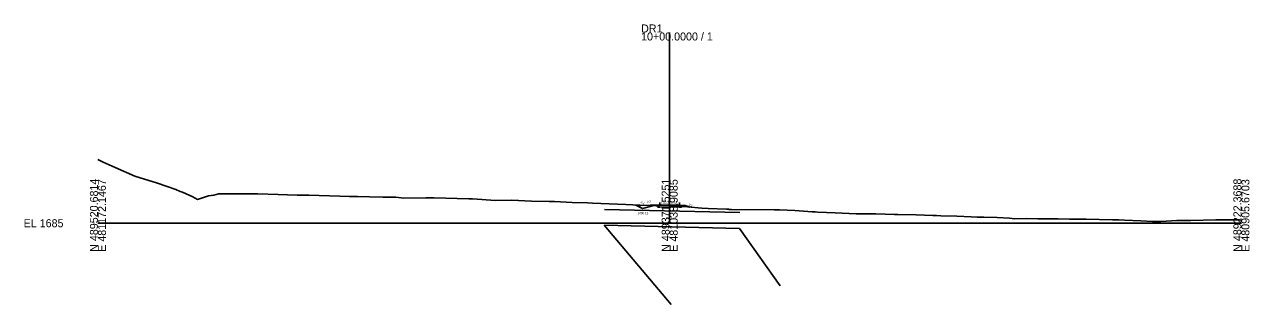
# Model space of a CAD drawing. Extents: x -26 to 403, y -28 to 1060.
# Drawn here: x -25.7 to 402.8, y -28.4 to 69.5 of the extents above; entities that cross this region are included whole.
import ezdxf

# ---------------------------------------------------------------- set-up
doc = ezdxf.new("R2010")
doc.units = 0
for name, color, linetype in [('Exist Cross Section Cell', 7, 'Continuous'), ('Exist XS Center Line Elevation Label', 7, 'Continuous'), ('Exist XS Ground Line', 7, 'Continuous'), ('Prop XS Ditch Slope Text', 7, 'Continuous'), ('Prop XS Ditch Standard Text', 7, 'Continuous'), ('Prop XS Dump Level', 7, 'Continuous'), ('Prop XS Earthwork Shape', 7, 'Continuous'), ('Prop XS EOT Tick Mark', 7, 'Continuous'), ('Prop XS Finish Grade', 7, 'Continuous'), ('Prop XS Finish Grade Earthwork', 7, 'Continuous'), ('Prop XS Finish Grade Pavement', 7, 'Continuous'), ('Prop XS Hydro Typical Ditch Data', 7, 'Continuous'), ('Prop XS Pvmt Edge Slope', 7, 'Continuous'), ('Prop XS SE Text', 7, 'Continuous'), ('Prop XS Shoulder Borrow Shape', 7, 'Continuous'), ('Prop XS Side Slope Text', 7, 'Continuous'), ('Prop XS Subgrade Earthwork', 7, 'Continuous'), ('Scratch_Level_4', 7, 'Continuous'), ('Scratch_Level_5', 7, 'Continuous')]:
    doc.layers.add(name, color=color, linetype=linetype)

msp = doc.modelspace()

# ---------------------------------------------------------------- linework, layer by layer
at = {"layer": 'Exist Cross Section Cell'}
for p, q in [((200, 0), (200, 66.75)), ((0, 0), (200, 0)), ((200, 0), (400, 0))]:
    msp.add_line(p, q, dxfattribs=at)
at = {"layer": 'Exist XS Ground Line'}
msp.add_lwpolyline([(0, 22.25), (1.77, 21.4), (6.02, 19.52), (12.85, 16.44), (20.87, 13.98), (27.26, 11.83), (28.74, 11.16), (29.57, 10.9), (33.18, 9.29), (34.8, 8.36), (36.61, 8.93), (38.72, 9.55), (40.5, 9.84), (42.12, 10.25), (55.9, 10.24), (63.02, 10.01), (66.27, 9.94), (69.66, 9.86), (73.77, 9.77), (77.43, 9.68), (84.67, 9.47), (87.93, 9.41), (90.85, 9.32), (95.02, 9.24), (99.69, 9.14), (102.1, 9.09), (104.26, 9.08), (107.06, 8.79), (114.7, 8.94), (116.27, 8.89), (117.67, 8.87), (129.71, 8.56), (130.44, 8.54), (131.08, 8.51), (139.03, 7.95), (144.73, 8.02), (151.69, 7.71), (157.9, 7.66), (158.77, 7.64), (159.74, 7.61), (165.85, 7.31), (171.31, 7.17), (173.03, 7.05), (184.72, 6.53), (189.54, 6.27), (189.96, 6.26), (196.5, 6.48), (197, 6.44), (198.06, 6.36), (200, 6.21), (203.43, 5.94), (206.2, 5.69), (211.29, 5.25), (213.44, 5.1), (219.9, 4.91), (220.54, 4.88), (220.86, 4.86), (221.68, 4.83), (236.69, 4.73), (238.37, 4.67), (243.77, 4.41), (249.82, 4), (250.86, 3.94), (251.78, 3.89), (257.94, 3.67), (265.19, 3.3), (272.11, 3.26), (278.6, 3.06), (279.19, 3.05), (279.85, 3.03), (286.28, 2.98), (292.02, 2.7), (293.36, 2.66), (294.86, 2.6), (300.44, 2.46), (305.43, 2.19), (307.53, 2.14), (309.88, 2.07), (314.61, 1.96), (318.84, 1.75), (320.78, 1.57), (324.89, 1.6), (328.78, 1.55), (332.25, 1.58), (335.86, 1.59), (339.91, 1.45), (342.95, 1.38), (345.66, 1.37), (354.92, 1.22), (357.11, 1.23), (359.07, 1.11), (364.85, 0.81), (368.95, 0.61), (371.84, 0.6), (377.47, 0.96), (382.26, 0.96), (391.05, 1.21), (399.29, 1.15), (400, 1.13)], dxfattribs=at)
at = {"layer": 'Prop XS Dump Level'}
for p, q in [((200, 6.38), (196.52, 6.31)), ((203.43, 6.31), (200, 6.38))]:
    msp.add_line(p, q, dxfattribs=at)
at = {"layer": 'Prop XS Earthwork Shape'}
for points in [[(203.43, 5.94), (204.34, 5.86), (204.11, 5.63), (203.43, 5.64), (200, 5.71), (196.52, 5.64), (195.83, 5.63), (195.25, 6.21), (194.51, 6.15), (190.51, 5.15), (188.11, 6.35), (189.54, 6.27), (189.96, 6.26), (196.5, 6.48), (197, 6.44), (198.06, 6.36), (200, 6.21)], [(204.34, 5.86), (206.2, 5.69), (207.01, 5.62), (205.43, 6.15), (204.69, 6.21)]]:
    msp.add_lwpolyline(points, close=True, dxfattribs=at)
at = {"layer": 'Prop XS EOT Tick Mark'}
for p, q in [((196.52, 6.31), (196.52, 7.31)), ((203.43, 6.31), (203.43, 7.31))]:
    msp.add_line(p, q, dxfattribs=at)
at = {"layer": 'Prop XS Finish Grade'}
for p, q in [((196.52, 6.31), (195.25, 6.21)), ((203.43, 6.31), (204.69, 6.21))]:
    msp.add_line(p, q, dxfattribs=at)
at = {"layer": 'Prop XS Finish Grade Earthwork'}
for p, q in [((190.51, 5.15), (188.11, 6.35)), ((194.51, 6.15), (190.51, 5.15)), ((195.25, 6.21), (194.51, 6.15)), ((204.69, 6.21), (205.43, 6.15)), ((205.43, 6.15), (207.01, 5.62))]:
    msp.add_line(p, q, dxfattribs=at)
at = {"layer": 'Prop XS Finish Grade Pavement'}
for p, q in [((196.52, 6.31), (200, 6.38)), ((200, 6.38), (203.43, 6.31))]:
    msp.add_line(p, q, dxfattribs=at)
at = {"layer": 'Prop XS Hydro Typical Ditch Data'}
for p, q in [((190.51, 5.15), (188.71, 6.05)), ((194.51, 6.15), (190.51, 5.15))]:
    msp.add_line(p, q, dxfattribs=at)
at = {"layer": 'Prop XS Pvmt Edge Slope'}
for p, q in [((196.52, 6.31), (195.83, 5.63)), ((203.43, 6.31), (204.11, 5.63))]:
    msp.add_line(p, q, dxfattribs=at)
at = {"layer": 'Prop XS Shoulder Borrow Shape'}
for points in [[(196.52, 6.31), (195.83, 5.63), (195.25, 6.21)], [(204.11, 5.63), (204.69, 6.21), (203.43, 6.31)]]:
    msp.add_lwpolyline(points, close=True, dxfattribs=at)
at = {"layer": 'Prop XS Subgrade Earthwork'}
for p, q in [((195.83, 5.63), (195.25, 6.21)), ((196.52, 5.64), (195.83, 5.63)), ((200, 5.71), (196.52, 5.64)), ((203.43, 5.64), (200, 5.71)), ((203.43, 5.64), (204.11, 5.63)), ((204.11, 5.63), (204.69, 6.21))]:
    msp.add_line(p, q, dxfattribs=at)
at = {"layer": 'Scratch_Level_4'}
for p, q in [((177.19, 4.85), (224.58, 3.7)), ((177.05, -0.65), (224.45, -1.8)), ((177.05, -0.65), (200.48, -28.44)), ((224.45, -1.8), (238.66, -21.89))]:
    msp.add_line(p, q, dxfattribs=at)
at = {"layer": 'Scratch_Level_5'}
msp.add_lwpolyline([(0, 22.25), (1.77, 21.4), (6.02, 19.52), (12.85, 16.44), (20.87, 13.98), (27.26, 11.83), (28.74, 11.16), (29.57, 10.9), (33.18, 9.29), (34.8, 8.36), (36.61, 8.93), (38.72, 9.55), (40.5, 9.84), (42.12, 10.25), (55.9, 10.24), (63.02, 10.01), (66.27, 9.94), (69.66, 9.86), (73.77, 9.77), (77.43, 9.68), (84.67, 9.47), (87.93, 9.41), (90.85, 9.32), (95.02, 9.24), (99.69, 9.14), (102.1, 9.09), (104.26, 9.08), (107.06, 8.79), (114.7, 8.94), (116.27, 8.89), (117.67, 8.87), (129.71, 8.56), (130.44, 8.54), (131.08, 8.51), (139.03, 7.95), (144.73, 8.02), (151.69, 7.71), (157.9, 7.66), (158.77, 7.64), (159.74, 7.61), (165.85, 7.31), (171.31, 7.17), (173.03, 7.05), (184.72, 6.53), (189.54, 6.27), (189.96, 6.26), (196.5, 6.48), (197, 6.44), (198.06, 6.36), (200, 6.21), (203.43, 5.94), (206.2, 5.69), (211.29, 5.25), (213.44, 5.1), (219.9, 4.91), (220.54, 4.88), (220.86, 4.86), (221.68, 4.83), (236.69, 4.73), (238.37, 4.67), (243.77, 4.41), (249.82, 4), (250.86, 3.94), (251.78, 3.89), (257.94, 3.67), (265.19, 3.3), (272.11, 3.26), (278.6, 3.06), (279.19, 3.05), (279.85, 3.03), (286.28, 2.98), (292.02, 2.7), (293.36, 2.66), (294.86, 2.6), (300.44, 2.46), (305.43, 2.19), (307.53, 2.14), (309.88, 2.07), (314.61, 1.96), (318.84, 1.75), (320.78, 1.57), (324.89, 1.6), (328.78, 1.55), (332.25, 1.58), (335.86, 1.59), (339.91, 1.45), (342.95, 1.38), (345.66, 1.37), (354.92, 1.22), (357.11, 1.23), (359.07, 1.11), (364.85, 0.81), (368.95, 0.61), (371.84, 0.6), (377.47, 0.96), (382.26, 0.96), (391.05, 1.21), (399.29, 1.15), (400, 1.13)], dxfattribs=at)

# ---------------------------------------------------------------- texts
at = {"layer": 'Exist Cross Section Cell'}
for s, p in [('DR1', (190, 66.75)), ('10+00.0000 / 1', (190, 63.95)), ('EL 1685', (-26, -1.4))]:
    msp.add_text(s, height=2.8, dxfattribs=at).set_placement(p)
for s, p in [('N 489520.6814', (0, -10)), ('E 481172.1467', (2.8, -10)), ('N 489371.5251', (200, -10)), ('E 481038.9085', (202.8, -10)), ('N 489222.3688', (400, -10)), ('E 480905.6703', (402.8, -10))]:
    msp.add_text(s, height=2.8, rotation=90, dxfattribs=at).set_placement(p)
at = {"layer": 'Exist XS Center Line Elevation Label'}
msp.add_text('1691.21', height=0.75, dxfattribs=at).set_placement((198.57, 1.46))
at = {"layer": 'Prop XS Ditch Slope Text'}
msp.add_text('4:1', height=0.75, rotation=14.0251, dxfattribs=at).set_placement((192.15, 7.1))
at = {"layer": 'Prop XS Ditch Standard Text'}
msp.add_text('1690.15', height=0.75, dxfattribs=at).set_placement((188.8, 3.16))
at = {"layer": 'Prop XS Dump Level'}
for p in [(194.51, 6.11), (205.43, 6.11)]:
    msp.add_text('Case1', height=0.04, dxfattribs=at).set_placement(p)
at = {"layer": 'Prop XS SE Text'}
for rotation, p in [(1.1458, (196.97, 6.82)), (358.8542, (200.42, 6.87))]:
    msp.add_text('0.020', height=0.75, rotation=rotation, dxfattribs=at).set_placement(p)
at = {"layer": 'Prop XS Side Slope Text'}
for s, rotation, p in [('2:1', 333.4538, (189.76, 7.2)), ('3:1', 341.5651, (206.55, 6.18))]:
    msp.add_text(s, height=0.75, rotation=rotation, dxfattribs=at).set_placement(p)

doc.saveas('drawing.dxf')
